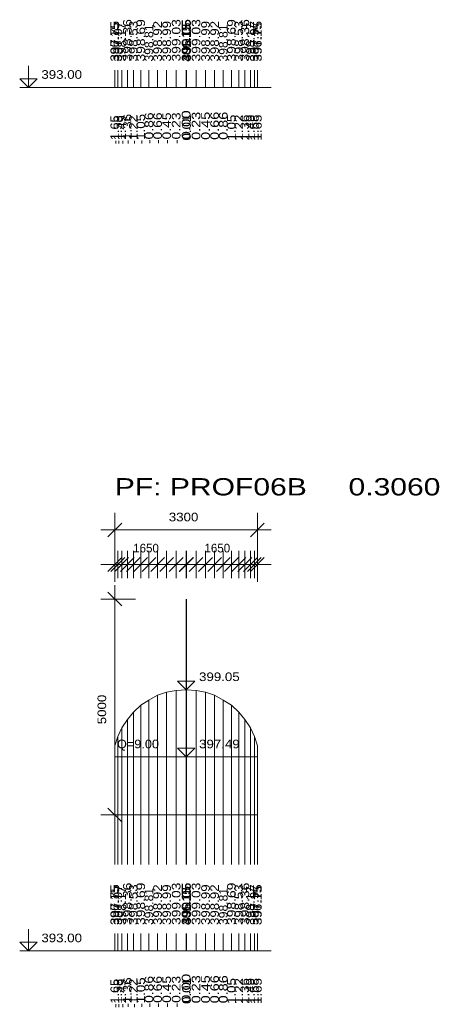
# Model space of a CAD drawing. Extents: x 7 to 442, y -393 to 441.
# Drawn here: x 297.79 to 307.49, y 19.89 to 42.77 of the extents above; entities that cross this region are included whole.
import ezdxf

# ---------------------------------------------------------------- set-up
doc = ezdxf.new("R2010")
doc.units = 0
doc.header["$LTSCALE"] = 0.08
doc.layers.add('7', color=7, linetype='Continuous', lineweight=13)

msp = doc.modelspace()

# ---------------------------------------------------------------- linework, layer by layer
at = {"layer": '7'}
for p, q in [((299.985, 41.2), (299.985, 41.6)), ((299.985, 41.2), (299.985, 41.6)), ((300.055, 41.2), (300.055, 41.6)), ((300.145, 41.2), (300.145, 41.6)), ((300.275, 41.2), (300.275, 41.6)), ((300.415, 41.2), (300.415, 41.6)), ((300.585, 41.2), (300.585, 41.6)), ((300.775, 41.2), (300.775, 41.6)), ((300.975, 41.2), (300.975, 41.6)), ((301.185, 41.2), (301.185, 41.6)), ((301.405, 41.2), (301.405, 41.6)), ((301.635, 41.2), (301.635, 41.6)), ((301.635, 41.2), (301.635, 41.6)), ((301.635, 41.2), (301.635, 41.6)), ((301.645, 41.2), (301.645, 41.6)), ((301.645, 41.2), (301.645, 41.6)), ((301.865, 41.2), (301.865, 41.6)), ((302.085, 41.2), (302.085, 41.6)), ((302.295, 41.2), (302.295, 41.6)), ((302.495, 41.2), (302.495, 41.6)), ((302.685, 41.2), (302.685, 41.6)), ((302.855, 41.2), (302.855, 41.6)), ((302.995, 41.2), (302.995, 41.6)), ((303.125, 41.2), (303.125, 41.6)), ((303.215, 41.2), (303.215, 41.6)), ((303.285, 41.2), (303.285, 41.6)), ((303.285, 41.2), (303.285, 41.6)), ((297.785, 41.2), (303.605, 41.2)), ((299.985, 29.75), (299.985, 31.35)), ((303.285, 29.75), (303.285, 31.35)), ((299.825, 30.79), (300.145, 31.11)), ((303.125, 30.79), (303.445, 31.11)), ((299.665, 30.95), (303.605, 30.95)), ((299.985, 29.83), (299.985, 30.47)), ((299.985, 29.83), (299.985, 30.47)), ((300.055, 29.83), (300.055, 30.47)), ((300.145, 29.83), (300.145, 30.47)), ((300.275, 29.83), (300.275, 30.47)), ((300.415, 29.83), (300.415, 30.47)), ((300.585, 29.83), (300.585, 30.47)), ((300.775, 29.83), (300.775, 30.47)), ((300.975, 29.83), (300.975, 30.47)), ((301.185, 29.83), (301.185, 30.47)), ((301.405, 29.83), (301.405, 30.47)), ((301.635, 29.83), (301.635, 30.47)), ((301.635, 29.83), (301.635, 30.47)), ((301.635, 29.83), (301.635, 30.47)), ((301.645, 29.83), (301.645, 30.47)), ((301.645, 29.83), (301.645, 30.47)), ((301.865, 29.83), (301.865, 30.47)), ((302.085, 29.83), (302.085, 30.47)), ((302.295, 29.83), (302.295, 30.47)), ((302.495, 29.83), (302.495, 30.47)), ((302.685, 29.83), (302.685, 30.47)), ((302.855, 29.83), (302.855, 30.47)), ((302.995, 29.83), (302.995, 30.47)), ((303.125, 29.83), (303.125, 30.47)), ((303.215, 29.83), (303.215, 30.47)), ((303.285, 29.83), (303.285, 30.47)), ((303.285, 29.83), (303.285, 30.47)), ((299.825, 29.99), (300.145, 30.31)), ((299.825, 29.99), (300.145, 30.31)), ((299.895, 29.99), (300.215, 30.31)), ((299.985, 29.99), (300.305, 30.31)), ((300.115, 29.99), (300.435, 30.31)), ((300.255, 29.99), (300.575, 30.31)), ((300.425, 29.99), (300.745, 30.31)), ((300.615, 29.99), (300.935, 30.31)), ((300.815, 29.99), (301.135, 30.31)), ((301.025, 29.99), (301.345, 30.31)), ((301.245, 29.99), (301.565, 30.31)), ((301.475, 29.99), (301.795, 30.31)), ((301.475, 29.99), (301.795, 30.31)), ((301.475, 29.99), (301.795, 30.31)), ((301.485, 29.99), (301.805, 30.31)), ((301.485, 29.99), (301.805, 30.31)), ((301.705, 29.99), (302.025, 30.31)), ((301.925, 29.99), (302.245, 30.31)), ((302.135, 29.99), (302.455, 30.31)), ((302.335, 29.99), (302.655, 30.31)), ((302.525, 29.99), (302.845, 30.31)), ((302.695, 29.99), (303.015, 30.31)), ((302.835, 29.99), (303.155, 30.31)), ((302.965, 29.99), (303.285, 30.31)), ((303.055, 29.99), (303.375, 30.31)), ((303.125, 29.99), (303.445, 30.31)), ((303.125, 29.99), (303.445, 30.31)), ((299.665, 30.15), (303.605, 30.15)), ((300.145, 29.19), (299.825, 29.51)), ((299.985, 24.19), (299.985, 29.67)), ((299.665, 29.35), (300.465, 29.35)), ((301.635, 23.2), (301.635, 29.35)), ((301.645, 23.2), (301.645, 29.35)), ((301.405, 23.2), (301.405, 27.23)), ((301.635, 23.2), (301.635, 27.25)), ((301.635, 27.25), (301.645, 27.25)), ((301.645, 23.2), (301.645, 27.25)), ((301.865, 23.2), (301.865, 27.23)), ((300.775, 23.2), (300.775, 27.01)), ((300.975, 23.2), (300.975, 27.12)), ((301.185, 23.2), (301.185, 27.19)), ((302.085, 23.2), (302.085, 27.19)), ((302.295, 23.2), (302.295, 27.12)), ((302.495, 23.2), (302.495, 27.01)), ((300.585, 23.2), (300.585, 26.89)), ((302.685, 23.2), (302.685, 26.89)), ((300.275, 23.2), (300.275, 26.56)), ((300.415, 23.2), (300.415, 26.73)), ((302.855, 23.2), (302.855, 26.73)), ((302.995, 23.2), (302.995, 26.56)), ((300.145, 23.2), (300.145, 26.37)), ((303.125, 23.2), (303.125, 26.37)), ((300.055, 23.2), (300.055, 26.17)), ((303.215, 23.2), (303.215, 26.17)), ((299.985, 23.2), (299.985, 25.95)), ((303.285, 23.2), (303.285, 25.95)), ((299.985, 25.693), (303.285, 25.693)), ((300.145, 24.19), (299.825, 24.51)), ((299.665, 24.35), (300.465, 24.35)), ((299.985, 23.2), (299.985, 24.35)), ((301.635, 23.2), (301.635, 24.35)), ((303.285, 23.2), (303.285, 24.35)), ((299.985, 21.2), (299.985, 21.6)), ((299.985, 21.2), (299.985, 21.6)), ((300.055, 21.2), (300.055, 21.6)), ((300.145, 21.2), (300.145, 21.6)), ((300.275, 21.2), (300.275, 21.6)), ((300.415, 21.2), (300.415, 21.6)), ((300.585, 21.2), (300.585, 21.6)), ((300.775, 21.2), (300.775, 21.6)), ((300.975, 21.2), (300.975, 21.6)), ((301.185, 21.2), (301.185, 21.6)), ((301.405, 21.2), (301.405, 21.6)), ((301.635, 21.2), (301.635, 21.6)), ((301.635, 21.2), (301.635, 21.6)), ((301.635, 21.2), (301.635, 21.6)), ((301.645, 21.2), (301.645, 21.6)), ((301.645, 21.2), (301.645, 21.6)), ((301.865, 21.2), (301.865, 21.6)), ((302.085, 21.2), (302.085, 21.6)), ((302.295, 21.2), (302.295, 21.6)), ((302.495, 21.2), (302.495, 21.6)), ((302.685, 21.2), (302.685, 21.6)), ((302.855, 21.2), (302.855, 21.6)), ((302.995, 21.2), (302.995, 21.6)), ((303.125, 21.2), (303.125, 21.6)), ((303.215, 21.2), (303.215, 21.6)), ((303.285, 21.2), (303.285, 21.6)), ((303.285, 21.2), (303.285, 21.6)), ((297.785, 21.2), (303.605, 21.2))]:
    msp.add_line(p, q, dxfattribs=at)
for points in [[(297.985, 41.7), (297.985, 41.2), (297.785, 41.4), (298.185, 41.4), (297.985, 41.2)], [(301.635, 29.35), (301.635, 27.25), (301.405, 27.23), (301.185, 27.19), (300.975, 27.12), (300.775, 27.01), (300.585, 26.89), (300.415, 26.73), (300.275, 26.56), (300.145, 26.37), (300.055, 26.17), (299.985, 25.95), (299.985, 24.35), (301.635, 24.35), (303.285, 24.35), (303.285, 25.95), (303.215, 26.17), (303.125, 26.37), (302.995, 26.56), (302.855, 26.73), (302.685, 26.89), (302.495, 27.01), (302.295, 27.12), (302.085, 27.19), (301.865, 27.23), (301.645, 27.25), (301.645, 29.35)], [(301.635, 27.75), (301.635, 27.25), (301.435, 27.45), (301.835, 27.45), (301.635, 27.25)], [(301.635, 26.193), (301.635, 25.693), (301.435, 25.893), (301.835, 25.893), (301.635, 25.693)], [(297.985, 21.7), (297.985, 21.2), (297.785, 21.4), (298.185, 21.4), (297.985, 21.2)]]:
    msp.add_lwpolyline(points, dxfattribs=at)

# ---------------------------------------------------------------- texts
for s, width, p in [('397.75 ', 1.15, (300.085, 41.8)), ('396.15 ', 1.1, (300.085, 41.8)), ('397.97 ', 1.15, (300.155, 41.8)), ('398.17 ', 1.1, (300.245, 41.8)), ('398.36 ', 1.2, (300.375, 41.8)), ('398.53 ', 1.15, (300.515, 41.8)), ('398.69 ', 1.2, (300.685, 41.8)), ('398.81 ', 1.05, (300.875, 41.8)), ('398.92 ', 1.15, (301.075, 41.8)), ('398.99 ', 1.15, (301.285, 41.8)), ('399.03 ', 1.2, (301.505, 41.8)), ('399.05 ', 1.2, (301.735, 41.8)), ('396.15 ', 1.1, (301.735, 41.8)), ('401.15 ', 1.05, (301.735, 41.8)), ('399.05 ', 1.2, (301.745, 41.8)), ('401.15 ', 1.05, (301.745, 41.8)), ('399.03 ', 1.2, (301.965, 41.8)), ('398.99 ', 1.15, (302.185, 41.8)), ('398.92 ', 1.15, (302.395, 41.8)), ('398.81 ', 1.05, (302.595, 41.8)), ('398.69 ', 1.2, (302.785, 41.8)), ('398.53 ', 1.15, (302.955, 41.8)), ('398.36 ', 1.2, (303.095, 41.8)), ('398.17 ', 1.1, (303.225, 41.8)), ('397.97 ', 1.15, (303.315, 41.8)), ('397.75 ', 1.15, (303.385, 41.8)), ('396.15 ', 1.1, (303.385, 41.8)), (' -1.65 ', 1.1, (300.085, 39.8)), (' -1.65 ', 1.1, (300.085, 39.8)), (' -1.58 ', 1.1, (300.155, 39.8)), (' -1.49 ', 1.1, (300.245, 39.8)), (' -1.36 ', 1.15, (300.375, 39.8)), (' -1.22 ', 1.1, (300.515, 39.8)), (' -1.05 ', 1.15, (300.685, 39.8)), (' -0.86 ', 1.2, (300.875, 39.8)), (' -0.66 ', 1.2, (301.075, 39.8)), (' -0.45 ', 1.2, (301.285, 39.8)), (' -0.23 ', 1.2, (301.505, 39.8)), ('  0.00 ', 1.3, (301.735, 39.8)), ('  0.00 ', 1.3, (301.735, 39.8)), ('  0.00 ', 1.3, (301.735, 39.8)), ('  0.01 ', 1.15, (301.745, 39.8)), ('  0.01 ', 1.15, (301.745, 39.8)), ('  0.23 ', 1.25, (301.965, 39.8)), ('  0.45 ', 1.25, (302.185, 39.8)), ('  0.66 ', 1.25, (302.395, 39.8)), ('  0.86 ', 1.25, (302.595, 39.8)), ('  1.05 ', 1.15, (302.785, 39.8)), ('  1.22 ', 1.15, (302.955, 39.8)), ('  1.36 ', 1.15, (303.095, 39.8)), ('  1.49 ', 1.15, (303.225, 39.8)), ('  1.58 ', 1.15, (303.315, 39.8)), ('  1.65 ', 1.15, (303.385, 39.8)), ('  1.65 ', 1.15, (303.385, 39.8)), ('5000', 1.15, (299.785, 26.45)), ('397.75 ', 1.15, (300.085, 21.8)), ('396.15 ', 1.1, (300.085, 21.8)), ('397.97 ', 1.15, (300.155, 21.8)), ('398.17 ', 1.1, (300.245, 21.8)), ('398.36 ', 1.2, (300.375, 21.8)), ('398.53 ', 1.15, (300.515, 21.8)), ('398.69 ', 1.2, (300.685, 21.8)), ('398.81 ', 1.05, (300.875, 21.8)), ('398.92 ', 1.15, (301.075, 21.8)), ('398.99 ', 1.15, (301.285, 21.8)), ('399.03 ', 1.2, (301.505, 21.8)), ('399.05 ', 1.2, (301.735, 21.8)), ('396.15 ', 1.1, (301.735, 21.8)), ('401.15 ', 1.05, (301.735, 21.8)), ('399.05 ', 1.2, (301.745, 21.8)), ('401.15 ', 1.05, (301.745, 21.8)), ('399.03 ', 1.2, (301.965, 21.8)), ('398.99 ', 1.15, (302.185, 21.8)), ('398.92 ', 1.15, (302.395, 21.8)), ('398.81 ', 1.05, (302.595, 21.8)), ('398.69 ', 1.2, (302.785, 21.8)), ('398.53 ', 1.15, (302.955, 21.8)), ('398.36 ', 1.2, (303.095, 21.8)), ('398.17 ', 1.1, (303.225, 21.8)), ('397.97 ', 1.15, (303.315, 21.8)), ('397.75 ', 1.15, (303.385, 21.8)), ('396.15 ', 1.1, (303.385, 21.8)), (' -0.86 ', 1.2, (300.875, 19.8)), (' -0.66 ', 1.2, (301.075, 19.8)), (' -0.45 ', 1.2, (301.285, 19.8)), (' -0.23 ', 1.2, (301.505, 19.8)), ('  0.00 ', 1.3, (301.735, 19.8)), ('  0.00 ', 1.3, (301.735, 19.8)), ('  0.00 ', 1.3, (301.735, 19.8)), ('  0.23 ', 1.25, (301.965, 19.8)), ('  0.45 ', 1.25, (302.185, 19.8)), ('  0.66 ', 1.25, (302.395, 19.8)), ('  0.86 ', 1.25, (302.595, 19.8)), (' -1.65 ', 1.1, (300.085, 19.8)), (' -1.65 ', 1.1, (300.085, 19.8)), (' -1.58 ', 1.1, (300.155, 19.8)), (' -1.49 ', 1.1, (300.245, 19.8)), (' -1.36 ', 1.15, (300.375, 19.8)), (' -1.22 ', 1.1, (300.515, 19.8)), (' -1.05 ', 1.15, (300.685, 19.8)), ('  0.01 ', 1.15, (301.745, 19.8)), ('  0.01 ', 1.15, (301.745, 19.8)), ('  1.05 ', 1.15, (302.785, 19.8)), ('  1.22 ', 1.15, (302.955, 19.8)), ('  1.36 ', 1.15, (303.095, 19.8)), ('  1.49 ', 1.15, (303.225, 19.8)), ('  1.58 ', 1.15, (303.315, 19.8)), ('  1.65 ', 1.15, (303.385, 19.8)), ('  1.65 ', 1.15, (303.385, 19.8))]:
    msp.add_text(s, height=0.2, rotation=90, dxfattribs=dict(at, width=width)).set_placement(p)
for s, height, width, p in [('393.00', 0.2, 1.15, (298.285, 41.4)), ('PF: PROF06B     0.3060', 0.4, 1.3, (299.985, 31.75)), ('3300', 0.2, 1.15, (301.235, 31.15)), ('399.05', 0.2, 1.15, (301.935, 27.45)), ('Q=9.00', 0.2, 1.1, (300.035, 25.893)), ('397.49', 0.2, 1.15, (301.935, 25.893)), ('393.00', 0.2, 1.15, (298.285, 21.4))]:
    msp.add_text(s, height=height, dxfattribs=dict(at, width=width)).set_placement(p)
for p in [(300.41, 30.43), (302.06, 30.43)]:
    msp.add_text('1650', height=0.2, dxfattribs=at).set_placement(p)

doc.saveas('drawing.dxf')
